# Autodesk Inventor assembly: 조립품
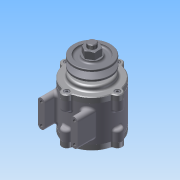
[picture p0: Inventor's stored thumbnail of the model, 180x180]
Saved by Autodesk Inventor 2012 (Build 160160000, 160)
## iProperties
Created: 2015-03
Part Number: 조립품
Document SubType Name: Assembly
Designer: net
Author: net
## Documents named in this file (11)
- C:\Users\net\Desktop\450305V1044\조립품.iam
- C:\Users\net\Desktop\450305V1044\본체.ipt
- C:\Users\net\Desktop\450305V1044\베어링 6204.ipt
- C:\Users\net\Desktop\450305V1044\축.ipt
- C:\Users\net\Desktop\450305V1044\키(4 x 4 x 12).ipt
- C:\Users\net\Desktop\450305V1044\V벨트풀리.ipt
- C:\Users\net\Desktop\450305V1044\커버.ipt
- C:\Users\net\Desktop\450305V1044\커버2.ipt
- C:\Users\net\Desktop\450305V1044\오일실.ipt
- C:\Users\net\Desktop\450305V1044\M 4 x 12.ipt
- C:\Users\net\Desktop\450305V1044\너트 M12x1.25.ipt
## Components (14 placed, 6 different names)
1. KS B 2023 6204 - 20 x 47 x 14:1
2. KS B 2023 6204 - 20 x 47 x 14:2
3. KS B 1311 (I) 4 x 4 x 12:1
4. 그루브 풀리1:1
5. KS B 2804 D D - 20 32 8:1
6. KS B 1012 클래스 1 일반 - 미터 M12x1.25:1
7. KS B 1003 - 미터 M 4 x 12:2
8. KS B 1003 - 미터 M 4 x 12:3
9. KS B 1003 - 미터 M 4 x 12:4
10. KS B 1003 - 미터 M 4 x 12:5
11. KS B 1003 - 미터 M 4 x 12:1
12. KS B 1003 - 미터 M 4 x 12:6
13. KS B 1003 - 미터 M 4 x 12:7
14. KS B 1003 - 미터 M 4 x 12:8
